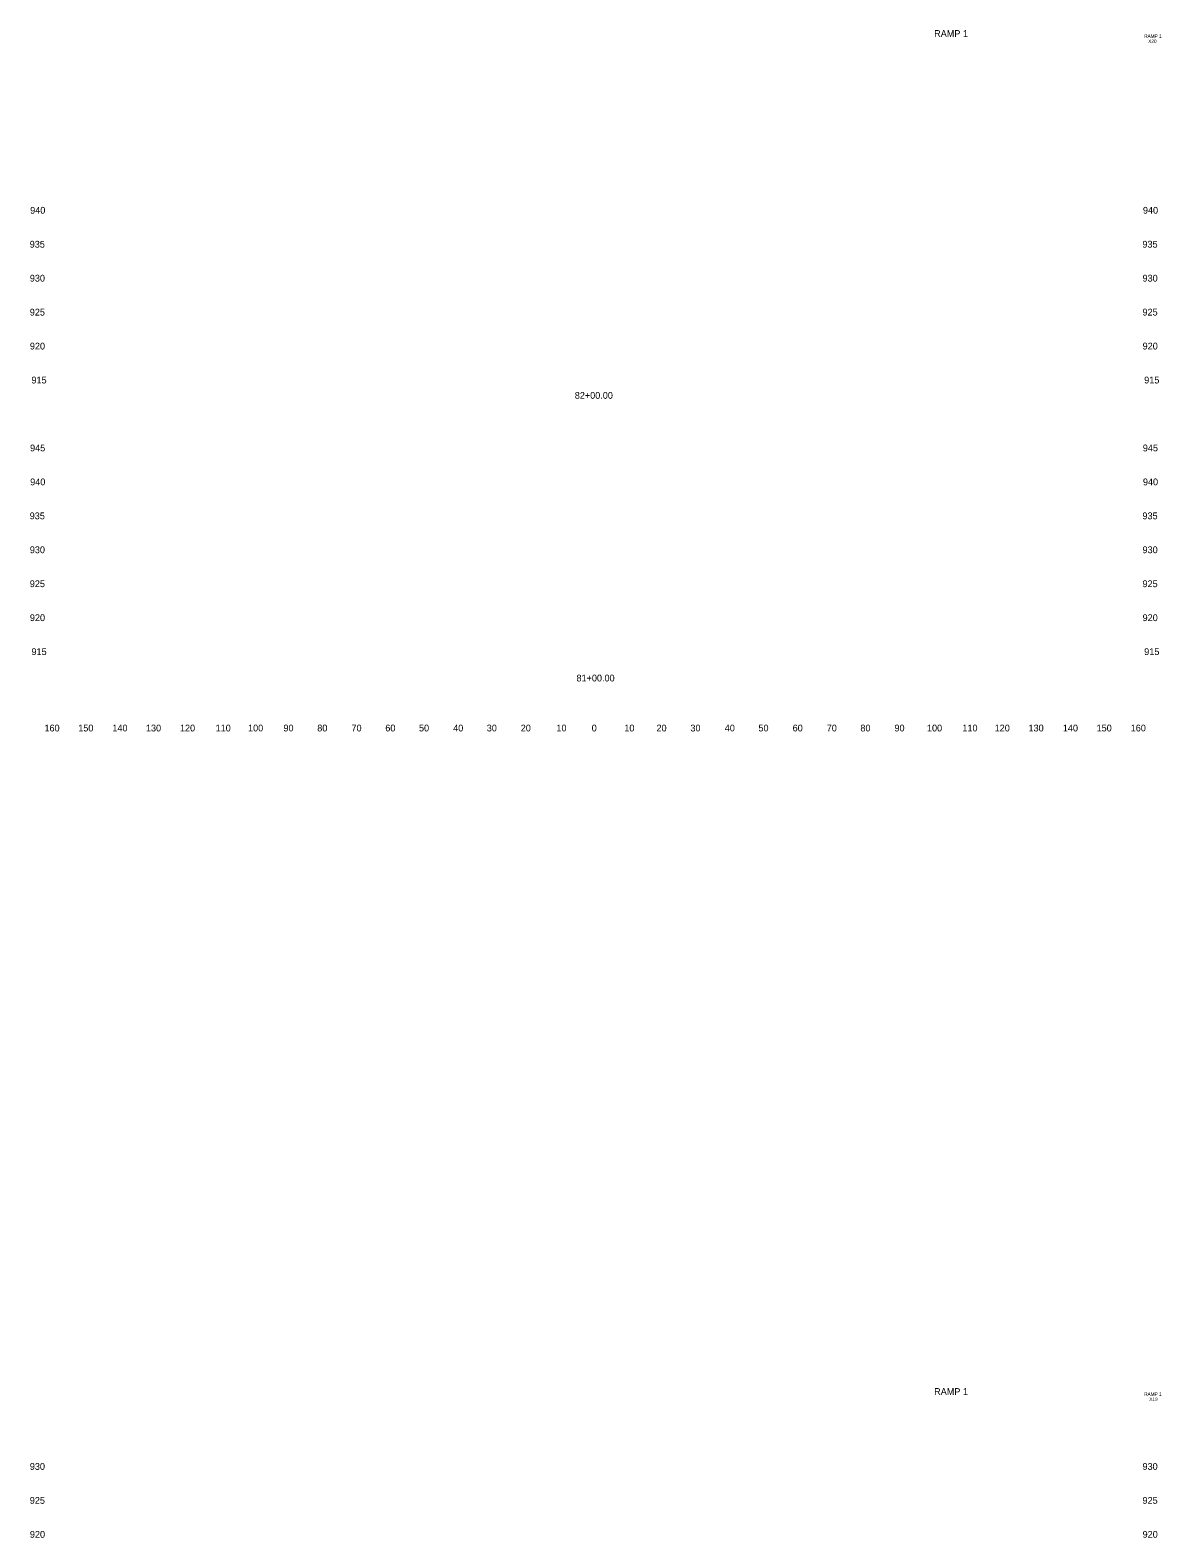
# Model space of a CAD drawing. Extents: x 4994 to 7869, y 4997 to 8804.
# Drawn here: x 5508.9 to 5842, y 8360 to 8804.1 of the extents above; entities that cross this region are included whole.
import ezdxf

# ---------------------------------------------------------------- set-up
doc = ezdxf.new("R2010")
doc.units = 0
for name, color, linetype in [('RD_SHT_ID', 7, 'Continuous'), ('RD_XS_TX_Offset', 7, 'Continuous'), ('RD_XS_TX_Station', 7, 'Continuous')]:
    doc.layers.add(name, color=color, linetype=linetype)

msp = doc.modelspace()

# ---------------------------------------------------------------- texts
at = {"layer": 'RD_SHT_ID'}
for s, height, p in [('RAMP 1', 2, (5775.19, 8802.06)), ('RAMP 1', 1, (5837.06, 8801.8)), ('X20', 1, (5838.25, 8800.3)), ('RAMP 1', 2, (5775.19, 8402.06)), ('RAMP 1', 1, (5837.06, 8401.8)), ('X19', 1, (5838.57, 8400.3))]:
    msp.add_text(s, height=height, dxfattribs=at).set_placement(p)
at = {"layer": 'RD_XS_TX_Offset'}
for s, p in [('940', (5508.89, 8750)), ('940', (5836.69, 8750)), ('935', (5508.75, 8740)), ('935', (5836.55, 8740)), ('930', (5508.78, 8730)), ('930', (5836.58, 8730)), ('925', (5508.77, 8720)), ('925', (5836.57, 8720)), ('920', (5508.8, 8710)), ('920', (5836.6, 8710)), ('915', (5509.27, 8700)), ('915', (5837.07, 8700)), ('945', (5508.86, 8680)), ('945', (5836.66, 8680)), ('940', (5508.89, 8670)), ('940', (5836.69, 8670)), ('935', (5508.75, 8660)), ('935', (5836.55, 8660)), ('930', (5508.78, 8650)), ('930', (5836.58, 8650)), ('925', (5508.77, 8640)), ('925', (5836.57, 8640)), ('920', (5508.8, 8630)), ('920', (5836.6, 8630)), ('915', (5509.27, 8620)), ('915', (5837.07, 8620)), ('160', (5513.1, 8597.5)), ('150', (5523.04, 8597.5)), ('140', (5533.1, 8597.5)), ('130', (5542.99, 8597.5)), ('120', (5553.01, 8597.5)), ('110', (5563.51, 8597.5)), ('100', (5573.07, 8597.5)), ('90', (5583.5, 8597.5)), ('80', (5593.46, 8597.5)), ('70', (5603.54, 8597.5)), ('60', (5613.5, 8597.5)), ('50', (5623.43, 8597.5)), ('40', (5633.5, 8597.5)), ('30', (5643.39, 8597.5)), ('20', (5653.4, 8597.5)), ('10', (5663.91, 8597.5)), ('0', (5674.3, 8597.5)), ('0', (5674.3, 8597.5)), ('10', (5683.91, 8597.5)), ('20', (5693.4, 8597.5)), ('30', (5703.39, 8597.5)), ('40', (5713.5, 8597.5)), ('50', (5723.43, 8597.5)), ('60', (5733.5, 8597.5)), ('70', (5743.54, 8597.5)), ('80', (5753.46, 8597.5)), ('90', (5763.5, 8597.5)), ('100', (5773.07, 8597.5)), ('110', (5783.51, 8597.5)), ('120', (5793.01, 8597.5)), ('130', (5802.99, 8597.5)), ('140', (5813.1, 8597.5)), ('150', (5823.04, 8597.5)), ('160', (5833.1, 8597.5)), ('930', (5508.78, 8380)), ('930', (5836.58, 8380)), ('925', (5508.77, 8370)), ('925', (5836.57, 8370)), ('920', (5508.8, 8360)), ('920', (5836.6, 8360))]:
    msp.add_text(s, height=2, dxfattribs=at).set_placement(p)
at = {"layer": 'RD_XS_TX_Station'}
for s, p in [('82+00.00', (5669.32, 8695.48)), ('81+00.00', (5669.83, 8612.22))]:
    msp.add_text(s, height=2, dxfattribs=at).set_placement(p)

doc.saveas('drawing.dxf')
